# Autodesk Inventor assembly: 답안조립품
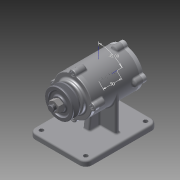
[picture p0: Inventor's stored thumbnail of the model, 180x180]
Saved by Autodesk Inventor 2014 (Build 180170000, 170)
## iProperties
Created: 2015-12
Part Number: 답안조립품
Document SubType Name: Assembly
Designer: L6
Author: L6
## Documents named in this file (11)
- C:\Users\L6\Desktop\451208V1001\답안조립품.iam
- C:\Users\L6\Desktop\451208V1001\본체.ipt
- C:\Users\L6\Desktop\451208V1001\V-벨트풀리.ipt
- C:\Users\L6\Desktop\451208V1001\너트 M12x1.25.ipt
- C:\Users\L6\Desktop\451208V1001\베어링 6204.ipt
- C:\Users\L6\Desktop\451208V1001\볼트 M4 x 12.ipt
- C:\Users\L6\Desktop\451208V1001\오일실.ipt
- C:\Users\L6\Desktop\451208V1001\축.ipt
- C:\Users\L6\Desktop\451208V1001\커버.ipt
- C:\Users\L6\Desktop\451208V1001\커버2.ipt
- C:\Users\L6\Desktop\451208V1001\키(4 x 4 x 12).ipt
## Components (6 placed, 5 different names)
1. V-벨트풀리:1 — 각도:3
2. KS B 1012 클래스 1 일반 - 미터 M12x1.25:1 — 각도:4
3. KS B 2023 6204 - 20 x 47 x 14:1
4. KS B 2804 D D - 20 32 8:1
5. KS B 1311 (I) 4 x 4 x 12:1 — 각도:3
6. KS B 2023 6204 - 20 x 47 x 14:2
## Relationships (2: Angle 2)
- 각도:3 [Angle]: V-벨트풀리:1 ↔ KS B 1311 (I) 4 x 4 x 12:1
- 각도:4 [Angle]: KS B 1012 클래스 1 일반 - 미터 M12x1.25:1
